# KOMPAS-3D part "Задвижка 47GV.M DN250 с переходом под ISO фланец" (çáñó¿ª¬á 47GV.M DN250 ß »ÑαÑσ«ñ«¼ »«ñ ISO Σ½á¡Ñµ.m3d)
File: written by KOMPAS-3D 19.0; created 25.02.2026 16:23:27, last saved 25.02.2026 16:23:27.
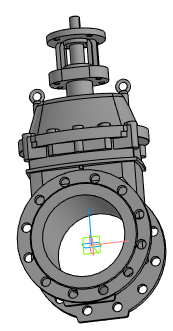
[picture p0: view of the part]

Document properties: Автор: Евгений; Полное имя файла: ..\..\47GVM\DR.47GVM.250.16.00.000\DR.47GVM.250.16.00.00 - Задвижка с обрезиненным клином DN250.a3d

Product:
- Part/product: Задвижка 47GV.M DN250 с переходом под ISO фланец
    Масса: 164.247
  - Component: Задвижка с обрезиненным клином DN250. Сборочный чертеж  | designation DR.47GVM.250.16.00.00СБ  | pos. 0  | Масса: 79.6129; Раздел спецификации: Документация; Форматы листов документа: 2xA3; source file: 47GV.M DN250\DR.47GVM.250.16.00.000 СБ - Задвижка с обрезиненным клином DN250.cdw

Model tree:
1. Операция без истории:1

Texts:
  Точка начала. Х
  Точка начала. Y
  Точка начала. Z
